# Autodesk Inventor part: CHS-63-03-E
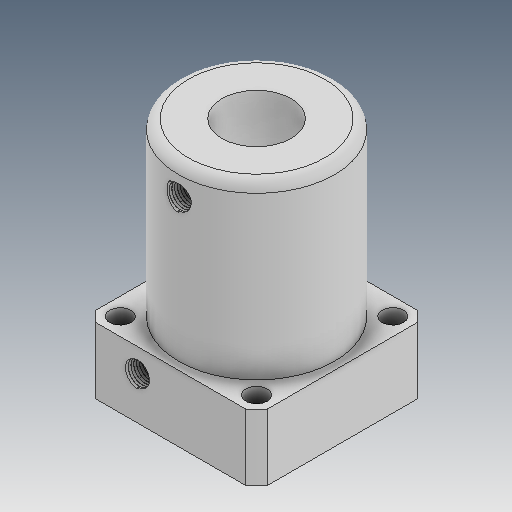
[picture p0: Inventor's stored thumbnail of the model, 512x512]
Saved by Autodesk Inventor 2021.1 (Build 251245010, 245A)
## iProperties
Created: 2019-05
Part Number: CHS-63-03-E
Material: Ogólny
Document SubType Name: Modeling
Designer: user
Density: 1 g/cm^3
Appearance: Domyślna
Author: user
Revision Number: ÈÎºÎ
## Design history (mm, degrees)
feature "ÊäÈë1"
node "Bryła1"
